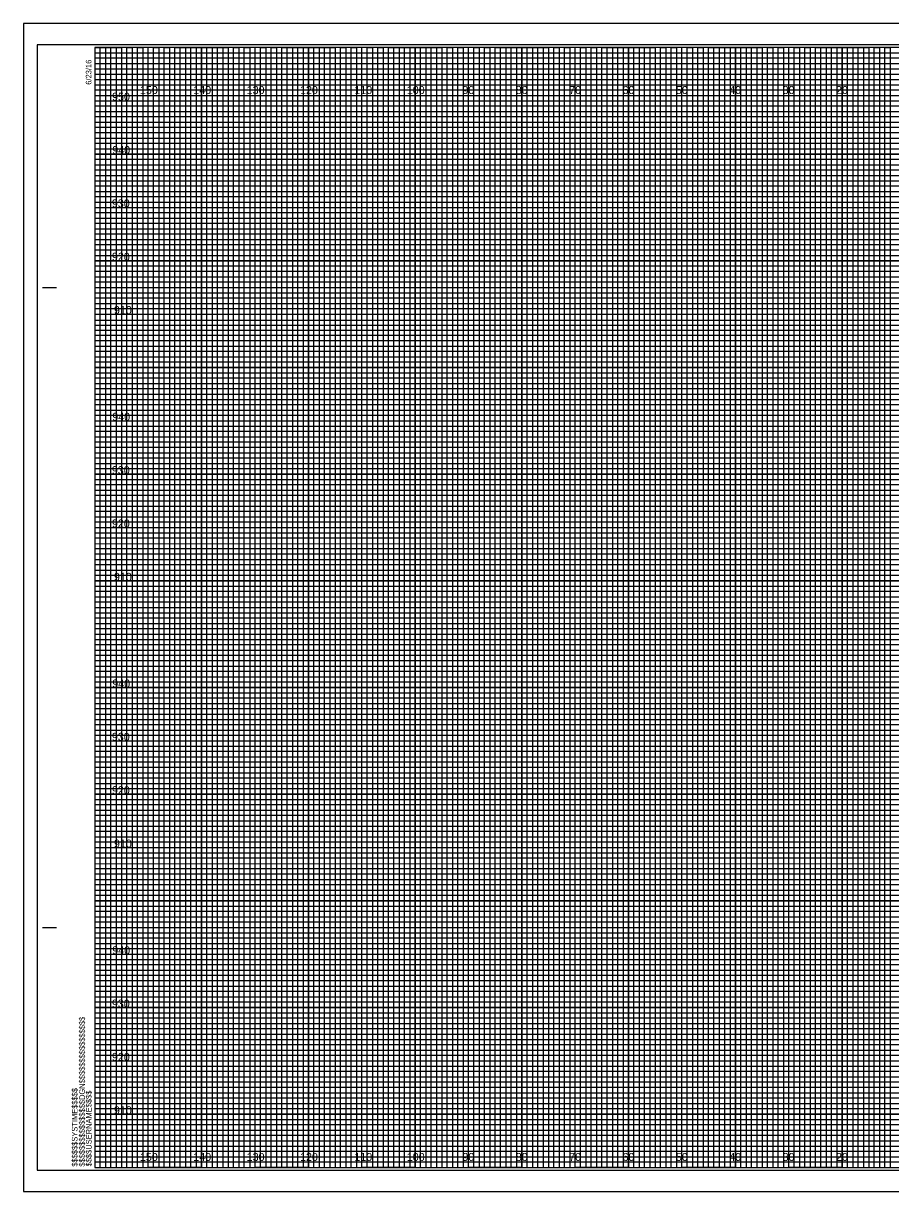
# Model space of a CAD drawing. Extents: x -13 to 323, y -4 to 3074.
# Drawn here: x -13.4 to 149.1, y 655.5 to 874.5 of the extents above; entities that cross this region are included whole.
import ezdxf

# ---------------------------------------------------------------- set-up
doc = ezdxf.new("R2010")
doc.units = 0
for name, color, linetype in [('Prop XS Elevation Labels', 7, 'Continuous'), ('Prop XS Offset Labels', 7, 'Continuous'), ('Sheet Cross Section CELL', 7, 'Continuous'), ('Sheet Cross Section Grid Major CELL', 7, 'Continuous'), ('Sheet Cross Section Grid Middle CELL', 7, 'Continuous'), ('Sheet Cross Section Grid Minor 1 CELL', 7, 'Continuous'), ('Sheet Cross Section Grid Minor 2 CELL', 7, 'Continuous'), ('Sheet Cutting Line CELL', 7, 'Continuous'), ('Sheet DOT Grid CELL', 7, 'Continuous'), ('Sheet Plot Border Inside CELL', 7, 'Continuous'), ('Sheet Plot Border Outside CELL', 7, 'Continuous')]:
    doc.layers.add(name, color=color, linetype=linetype)

msp = doc.modelspace()

# ---------------------------------------------------------------- linework, layer by layer
at = {"layer": 'Sheet Cross Section CELL'}
for p, q in [((-9.8, 825), (-7.3, 825)), ((-9.7, 825), (-7.2, 825)), ((-9.8, 705), (-7.3, 705)), ((-9.7, 705), (-7.2, 705)), ((0, 660), (0, 660)), ((0, 660), (0, 660)), ((0, 660), (0, 660)), ((0, 660), (0, 660)), ((0, 660), (0, 660)), ((0, 660), (0, 660)), ((0, 660), (0, 660))]:
    msp.add_line(p, q, dxfattribs=at)
msp.add_lwpolyline([(320, 870), (0, 870), (0, 660), (320, 660)], close=True, dxfattribs=at)
at = {"layer": 'Sheet Cross Section Grid Major CELL'}
for p, q in [((10, 870), (0, 870)), ((10, 660), (10, 870)), ((30, 870), (20, 870)), ((20, 870), (20, 660)), ((30, 660), (30, 870)), ((50, 870), (40, 870)), ((40, 870), (40, 660)), ((50, 660), (50, 870)), ((70, 870), (60, 870)), ((60, 870), (60, 660)), ((70, 660), (70, 870)), ((90, 870), (80, 870)), ((80, 870), (80, 660)), ((90, 660), (90, 870)), ((110, 870), (100, 870)), ((100, 870), (100, 660)), ((110, 660), (110, 870)), ((130, 870), (120, 870)), ((120, 870), (120, 660)), ((130, 660), (130, 870)), ((150, 870), (140, 870)), ((140, 870), (140, 660)), ((20, 660), (10, 660)), ((40, 660), (30, 660)), ((60, 660), (50, 660)), ((80, 660), (70, 660)), ((100, 660), (90, 660)), ((120, 660), (110, 660)), ((140, 660), (130, 660))]:
    msp.add_line(p, q, dxfattribs=at)
for points in [[(0, 860), (320, 860), (320, 850), (0, 850)], [(0, 840), (320, 840), (320, 830), (0, 830)], [(0, 820), (320, 820), (320, 810), (0, 810)], [(0, 800), (320, 800), (320, 790), (0, 790)], [(0, 780), (320, 780), (320, 770), (0, 770)], [(0, 760), (320, 760), (320, 750), (0, 750)], [(0, 740), (320, 740), (320, 730), (0, 730)], [(0, 720), (320, 720), (320, 710), (0, 710)], [(0, 700), (320, 700), (320, 690), (0, 690)], [(0, 680), (320, 680), (320, 670), (0, 670)]]:
    msp.add_lwpolyline(points, dxfattribs=at)
at = {"layer": 'Sheet Cross Section Grid Middle CELL'}
for points in [[(0, 870), (5, 870), (5, 660), (15, 660), (15, 870), (25, 870), (25, 660), (35, 660), (35, 870), (45, 870), (45, 660), (55, 660), (55, 870), (65, 870), (65, 660), (75, 660), (75, 870), (85, 870), (85, 660), (95, 660), (95, 870), (105, 870), (105, 660), (115, 660), (115, 870), (125, 870), (125, 660), (135, 660), (135, 870), (145, 870), (145, 660), (155, 660)], [(0, 865), (275, 865)], [(0, 845), (320, 845), (320, 855), (0, 855)], [(0, 825), (320, 825), (320, 835), (0, 835)], [(0, 805), (320, 805), (320, 815), (0, 815)], [(0, 785), (320, 785), (320, 795), (0, 795)], [(0, 765), (320, 765), (320, 775), (0, 775)], [(0, 745), (320, 745), (320, 755), (0, 755)], [(0, 725), (320, 725), (320, 735), (0, 735)], [(0, 705), (320, 705), (320, 715), (0, 715)], [(0, 685), (320, 685), (320, 695), (0, 695)], [(0, 665), (320, 665), (320, 675), (0, 675)]]:
    msp.add_lwpolyline(points, dxfattribs=at)
at = {"layer": 'Sheet Cross Section Grid Minor 1 CELL'}
for p, q in [((0, 869), (260, 869)), ((260, 867.98), (0, 867.98)), ((0, 867.98), (0, 867)), ((0, 867), (260, 867)), ((260, 865.89), (0, 865.89)), ((0, 865.89), (0, 864)), ((0, 864), (320, 864))]:
    msp.add_line(p, q, dxfattribs=at)
for points in [[(0, 863), (270, 863), (320, 863), (320, 862), (0, 862)], [(0, 861), (320, 861), (320, 859), (0, 859)], [(0, 858), (320, 858), (320, 857), (0, 856.98)], [(0, 856), (320, 856), (320, 854), (0, 854)], [(0, 853), (320, 853), (320, 852), (0, 852)], [(0, 851), (320, 851), (320, 849), (0, 849)], [(0, 848), (320, 848), (320, 847), (0, 847)], [(0, 846), (320, 846), (320, 844), (0, 844)], [(0, 843), (320, 843), (320, 842), (0, 842)], [(0, 841), (320, 841), (320, 839), (0, 839)], [(0, 838), (320, 838), (320, 837), (0, 837)], [(0, 836), (320, 836), (320, 833.95), (320, 833), (320, 832), (0, 832)], [(0, 834), (320, 834), (320, 833), (0, 833)], [(0, 831), (320, 831), (320, 829), (0, 829.03)], [(0, 829.03), (320, 829), (320, 828), (0, 828)], [(0, 827), (320, 827), (320, 826), (0, 826)], [(0, 824), (320, 824), (320, 823), (0, 823)], [(0, 822), (320, 822), (320, 821), (0, 821)], [(-0.07, 818.89), (320, 818.89), (320, 817.88), (-0.07, 817.88)], [(0, 817), (320, 817), (320, 816), (0, 816)], [(0, 814), (320, 814), (320, 813), (0, 813)], [(0, 812), (320, 812), (320, 811), (0, 811)], [(0, 809), (320, 809), (320, 808), (0, 808)], [(0, 807), (320, 807), (320, 806), (0, 806)], [(0, 804), (320, 804), (320, 803), (0, 803)], [(0, 802), (320, 802), (320, 801), (0, 801)], [(0, 799), (320, 799), (319.99, 797.98), (0, 798)], [(0, 797), (320, 797), (320, 796), (0, 796)], [(0, 794), (320, 794), (320, 793), (0, 793)], [(0, 792), (320, 792), (320, 791), (0, 791)], [(0, 789), (320, 789), (320, 788), (0, 788)], [(0, 787), (320, 787), (320, 786), (0, 786)], [(0, 784), (320, 784), (320, 783), (0, 783)], [(0, 782), (320, 782), (320, 781), (0, 781)], [(0, 779), (320, 779), (320, 778), (0, 778)], [(0, 776.99), (320.07, 776.91), (320, 776), (0, 776)], [(0, 774), (320, 774), (320, 773), (0, 773)], [(0, 772), (320, 772), (320, 771), (0, 771)], [(0, 769), (320, 769), (320, 768), (0, 768)], [(0, 767), (320, 767), (320, 766), (0, 766)], [(0, 764), (320, 764), (320, 763), (0, 763)], [(0, 762), (320, 762), (320, 761), (0, 761)], [(0, 759), (320, 759), (320, 758), (0, 758)], [(0, 757), (320, 757), (320, 756), (0, 756)], [(0, 754), (320, 754), (320, 753), (0, 753)], [(0, 752), (320, 752), (320, 751), (0, 751)], [(0, 749), (320, 749), (320, 748), (0, 748)], [(0, 747), (320, 747), (320, 746), (0, 746)], [(0, 744), (320, 744), (320, 743), (0, 743)], [(0, 742), (320, 742), (320, 741), (0, 741)], [(0, 739), (320, 739), (319.99, 737.98), (0, 738)], [(0, 737), (320, 737), (320, 736), (0, 736)], [(0, 734), (320, 734), (320, 733), (0, 733)], [(0, 732), (320, 732), (320, 731), (0, 731)], [(0, 729), (320, 729), (320, 728), (0, 728)], [(0, 727), (320, 727), (320, 726), (0, 726)], [(0, 724), (320, 724), (320, 723), (0, 723)], [(0, 722), (320, 722), (320, 721), (0, 721)], [(0, 719), (320, 719), (320, 718), (0, 718)], [(0, 716.99), (320.07, 716.91), (320, 716), (0, 716)], [(0, 714), (320, 714), (320, 713), (0, 713)], [(0, 712), (320, 712), (320, 711), (0, 711)], [(0, 709), (320, 709), (320, 708), (0, 708)], [(0, 707), (320, 707), (320, 706), (0, 706)], [(0, 704), (320, 704), (320, 703), (0, 703)], [(0, 702), (320, 702), (320, 701), (0, 701)], [(0, 699), (320, 699), (320, 698), (0, 698)], [(0, 697), (320, 697), (320, 696), (0, 696)], [(0, 694), (320, 694), (320, 693), (0, 693)], [(0, 692), (320, 692), (320, 691), (0, 691)], [(0, 689), (320, 689), (320, 688), (0, 688)], [(0, 687), (320, 687), (320, 686), (0, 686)], [(0, 684), (320, 684), (320, 683), (0, 683)], [(0, 682), (320, 682), (320, 681), (0, 681)], [(0, 679), (320, 679), (320, 678), (0, 678)], [(0, 677), (320, 677), (320, 676), (0, 676)], [(0, 674), (320, 674), (320, 673), (0, 673)], [(0, 672), (320, 672), (320, 671), (0, 671)], [(0, 669), (320, 669), (320, 668), (0, 668)], [(0, 667), (320, 667), (320, 666), (0, 666)], [(0, 664), (320, 664), (320, 663), (0, 663)], [(0, 662), (320, 662), (320, 661), (0, 661)]]:
    msp.add_lwpolyline(points, dxfattribs=at)
at = {"layer": 'Sheet Cross Section Grid Minor 2 CELL'}
for points in [[(0, 660), (1, 660), (1, 870), (2, 870), (2, 660)], [(2, 660), (3, 660), (3, 870), (4, 870), (4, 660)], [(5, 660), (6, 660), (6, 870), (7, 870), (7, 660)], [(7, 660), (8, 660), (8, 870), (9, 870), (9, 660)], [(10, 660), (11, 660), (11, 870), (12, 870), (12, 660)], [(12, 660), (13, 660), (13, 870), (14, 870), (14, 660)], [(15, 660), (16, 660), (16, 870), (17, 870), (17, 660)], [(17, 660), (18, 660), (18, 870), (19, 870), (19, 660)], [(20, 660), (21, 660), (21, 870), (22, 870), (22, 660)], [(22, 660), (23, 660), (23, 870), (24, 870), (24, 660)], [(25, 660), (26, 660), (26, 870), (27, 870), (27, 660)], [(27, 660), (28, 660), (28, 870), (29, 870), (29, 660)], [(30, 660), (31, 660), (31, 870), (32, 870), (32, 660)], [(32, 660), (33, 660), (33, 870), (34, 870), (34, 660)], [(35, 660), (36, 660), (36, 870), (37, 870), (37, 660)], [(37, 660), (38, 660), (38, 870), (39, 870), (39, 660)], [(40, 660), (41, 660), (41, 870), (42, 870), (42, 660)], [(42, 660), (43, 660), (43, 870), (44, 870), (44, 660)], [(45, 660), (46, 660), (46, 870), (47, 870), (47, 660)], [(47, 660), (48, 660), (48, 870), (49, 870), (49, 660)], [(50, 660), (51, 660), (51, 870), (52, 870), (52, 660)], [(52, 660), (53, 660), (53, 870), (54, 870), (54, 660)], [(55, 660), (56, 660), (56, 870), (57, 870), (57, 660)], [(57, 660), (58, 660), (58, 870), (59, 870), (59, 660)], [(60, 660), (61, 660), (61, 870), (62, 870), (62, 660)], [(62, 660), (63, 660), (63, 870), (64, 870), (64, 660)], [(65, 660), (66, 660), (66, 870), (67, 870), (67, 660)], [(67, 660), (68, 660), (68, 870), (69, 870), (69, 660)], [(70, 660), (71, 660), (71, 870), (72, 870), (72, 660)], [(72, 660), (73, 660), (73, 870), (74, 870), (74, 660)], [(75, 660), (76, 660), (76, 870), (77, 870), (77, 660)], [(77, 660), (78, 660), (78, 870), (79, 870), (79, 660)], [(80, 660), (81, 660), (81, 870), (82, 870), (82, 660)], [(82, 660), (83, 660), (83, 870), (84, 870), (84, 660)], [(85, 660), (86, 660), (86, 870), (87, 870), (87, 660)], [(87, 660), (88, 660), (88, 870), (89, 870), (89, 660)], [(90, 660), (91, 660), (91, 870), (92, 870), (92, 660)], [(92, 660), (93, 660), (93, 870), (94, 870), (94, 660)], [(95, 660), (96, 660), (96, 870), (97, 870), (97, 660)], [(97, 660), (98, 660), (98, 870), (99, 870), (99, 660)], [(100, 660), (101, 660), (101, 870), (102, 870), (102, 660)], [(102, 660), (103, 660), (103, 870), (104, 870), (104, 660)], [(105, 660), (106, 660), (106, 870), (107, 870), (107, 660)], [(107, 660), (108, 660), (108, 870), (109, 870), (109, 660)], [(110, 660), (111, 660), (111, 870), (112, 870), (112, 660)], [(112, 660), (113, 660), (113, 870), (114, 870), (114, 660)], [(115, 660), (116, 660), (116, 870), (117, 870), (117, 660)], [(117, 660), (118, 660), (118, 870), (119, 870), (119, 660)], [(120, 660), (121, 660), (121, 870), (122, 870), (122, 660)], [(122, 660), (123, 660), (123, 870), (124, 870), (124, 660)], [(125, 660), (126, 660), (126, 870), (127, 870), (127, 660)], [(127, 660), (128, 660), (128, 870), (129, 870), (129, 660)], [(130, 660), (131, 660), (131, 870), (132, 870), (132, 660)], [(132, 660), (133, 660), (133, 870), (134, 870), (134, 660)], [(135, 660), (136, 660), (136, 870), (137, 870), (137, 660)], [(137, 660), (138, 660), (138, 870), (139, 870), (139, 660)], [(140, 660), (141, 660), (141, 870), (142, 870), (142, 660)], [(142, 660), (143, 660), (143, 870), (144, 870), (144, 660)], [(145, 660), (146, 660), (146, 870), (147, 870), (147, 660)], [(147, 660), (148, 660), (148, 870), (149, 870), (149, 660)]]:
    msp.add_lwpolyline(points, dxfattribs=at)
at = {"layer": 'Sheet Cutting Line CELL'}
for p, q in [((323.3, 874.5), (-13.4, 874.5)), ((-13.4, 874.5), (-13.4, 655.5)), ((-13.4, 655.5), (323.3, 655.5))]:
    msp.add_line(p, q, dxfattribs=at)
at = {"layer": 'Sheet DOT Grid CELL'}
for p, q in [((10, 660), (10, 870)), ((20, 660), (20, 870)), ((30, 660), (30, 870)), ((40, 660), (40, 870)), ((50, 660), (50, 870)), ((60, 660), (60, 870)), ((70, 660), (70, 870)), ((80, 660), (80, 870)), ((90, 660), (90, 870)), ((100, 660), (100, 870)), ((110, 660), (110, 870)), ((120, 660), (120, 870)), ((130, 660), (130, 870)), ((140, 660), (140, 870)), ((0, 860), (320, 860)), ((0, 850), (320, 850)), ((0, 840), (320, 840)), ((0, 830), (320, 830)), ((0, 820), (320, 820)), ((0, 810), (320, 810)), ((0, 800), (320, 800)), ((0, 790), (320, 790)), ((0, 780), (320, 780)), ((0, 770), (320, 770)), ((0, 760), (320, 760)), ((0, 750), (320, 750)), ((0, 740), (320, 740)), ((0, 730), (320, 730)), ((0, 720), (320, 720)), ((0, 710), (320, 710)), ((0, 700), (320, 700)), ((0, 690), (320, 690)), ((0, 680), (320, 680)), ((0, 670), (320, 670))]:
    msp.add_line(p, q, dxfattribs=at)
at = {"layer": 'Sheet Plot Border Inside CELL'}
msp.add_lwpolyline([(-10.8, 659.5), (322.4, 659.5), (322.4, 870.5), (-10.8, 870.5)], close=True, dxfattribs=at)
at = {"layer": 'Sheet Plot Border Outside CELL'}
msp.add_lwpolyline([(-13.4, 655.5), (323.3, 655.5), (323.3, 874.5), (-13.4, 874.5)], close=True, dxfattribs=at)

# ---------------------------------------------------------------- texts
at = {"layer": 'Prop XS Elevation Labels'}
for s, p in [('950', (3.22, 860)), ('940', (3.26, 850)), ('930', (3.18, 840)), ('920', (3.19, 830)), ('910', (3.57, 820)), ('940', (3.26, 800)), ('930', (3.18, 790)), ('920', (3.19, 780)), ('910', (3.57, 770)), ('940', (3.26, 750)), ('930', (3.18, 740)), ('920', (3.19, 730)), ('910', (3.57, 720)), ('940', (3.26, 700)), ('930', (3.18, 690)), ('920', (3.19, 680)), ('910', (3.57, 670))]:
    msp.add_text(s, height=1.5, dxfattribs=at).set_placement(p)
at = {"layer": 'Prop XS Offset Labels'}
for s, p in [('150', (8.44, 861.25)), ('140', (18.44, 861.25)), ('130', (28.44, 861.25)), ('120', (38.44, 861.25)), ('110', (48.62, 861.25)), ('100', (58.44, 861.25)), ('90', (68.86, 861.25)), ('80', (78.86, 861.25)), ('70', (88.86, 861.25)), ('60', (98.86, 861.25)), ('50', (108.86, 861.25)), ('40', (118.86, 861.25)), ('30', (128.86, 861.25)), ('20', (138.86, 861.25)), ('150', (8.44, 661.25)), ('140', (18.44, 661.25)), ('130', (28.44, 661.25)), ('120', (38.44, 661.25)), ('110', (48.62, 661.25)), ('100', (58.44, 661.25)), ('90', (68.86, 661.25)), ('80', (78.86, 661.25)), ('70', (88.86, 661.25)), ('60', (98.86, 661.25)), ('50', (108.86, 661.25)), ('40', (118.86, 661.25)), ('30', (128.86, 661.25)), ('20', (138.86, 661.25))]:
    msp.add_text(s, height=1.5, dxfattribs=at).set_placement(p)
at = {"layer": 'Sheet Cross Section CELL'}
for s, p in [('6/23/16', (-0.65, 863)), ('$$$$$$$$$$$$$$$$DGN$$$$$$$$$$$$$$$$', (-1.88, 660.18)), ('$$$$$$SYSTIME$$$$$', (-3.26, 660.18)), ('$$$$USERNAME$$$$', (-0.62, 660.23))]:
    msp.add_text(s, height=1.05, rotation=90, dxfattribs=at).set_placement(p)

doc.saveas('drawing.dxf')
